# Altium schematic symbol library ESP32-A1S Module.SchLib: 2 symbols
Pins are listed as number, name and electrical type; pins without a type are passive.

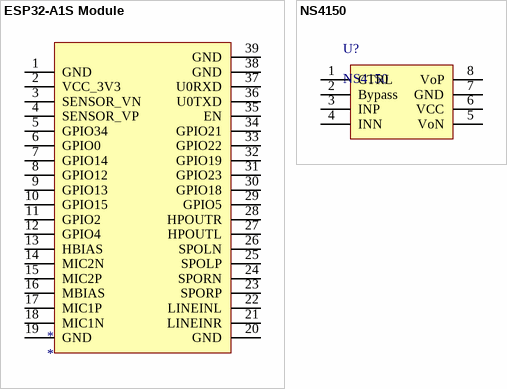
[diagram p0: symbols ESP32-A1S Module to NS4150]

## ESP32-A1S Module
designator *
pins: 1 GND, 2 VCC_3V3, 3 SENSOR_VN, 4 SENSOR_VP, 5 GPIO34, 6 GPIO0, 7 GPIO14, 8 GPIO12, 9 GPIO13, 10 GPIO15, 11 GPIO2, 12 GPIO4, 13 HBIAS, 14 MIC2N, 15 MIC2P, 16 MBIAS, 17 MIC1P, 18 MIC1N, 19 GND, 20 GND, 21 LINEINR, 22 LINEINL, 23 SPORP, 24 SPORN, 25 SPOLP, 26 SPOLN, 27 HPOUTL, 28 HPOUTR, 29 GPIO5, 30 GPIO18, 31 GPIO23, 32 GPIO19, 33 GPIO22, 34 GPIO21, 35 EN, 36 U0TXD, 37 U0RXD, 38 GND, 39 GND

## NS4150
designator U?
pins: 1 CTRL, 2 Bypass, 3 INP, 4 INN, 5 VoN, 6 VCC, 7 GND, 8 VoP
